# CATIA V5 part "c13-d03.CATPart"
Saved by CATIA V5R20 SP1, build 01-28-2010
Part number: Part1
Bounding box of the stored display mesh (mm): x 0 to 136, y 0 to 120, z 0 to 120
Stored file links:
  D:\v5_r20\psrt_files_downloaded\c13-catia-v5r20-prt\c13-catia-v5r20-figr-13-15 & 16\c13-d03.CATPart
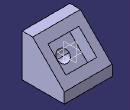
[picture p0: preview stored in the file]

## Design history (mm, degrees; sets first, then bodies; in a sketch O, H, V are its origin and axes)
Body1 (main body)
  Sketch1 on yz-plane, origin (0, 0, 0), H (0, 1, 0), V (0, 0, 1)
    line L1 (0, 0) -> (0, 120)
    line L2 (0, 120) -> (30, 120)
    line L3 (30, 120) -> (120, 30)
    line L4 (120, 30) -> (120, 0)
    point P4 (120, 0)
    line L5 (120, 0) -> (0, 0)
    length L1 = 120
    length L5 = 120
    length L4 = 30
    length L2 = 30
    vertical: L1 V, L4 V
    horizontal: L2 H, L5 H
    coincidence: P4 H
  Pad1: profile Sketch1, direction (1, 0, 0), length 136
  Sketch2 on face of Pad1, origin (0, 75, 75), H (-1, 0, 0), V (0, -0.7071, 0.7071)
    line L1 (-111.9577, 36.0679) -> (-24.0423, 36.0679)
    line L2 (-24.0423, 36.0679) -> (-24.0423, -36.0679)
    line L3 (-24.0423, -36.0679) -> (-111.9577, -36.0679)
    line L4 (-111.9577, -36.0679) -> (-111.9577, 36.0679)
    construction line L5 (-136, 63.6396) -> (0, -63.6396)
    point P5 (-136, 63.6396)
    point P6 (0, -63.6396)
    reference projected point E1 (0, -63.6396) from vertex [face of Pad1 | face of Pad1 | face of Pad1]
    reference projected point E2 (-136, 63.6396) from vertex [face of Pad1 | face of Pad1 | face of Pad1]
    axis line L6 (-111.9577, -36.0679) -> (-24.0423, 36.0679)
    point P7 (-68, 0)
    horizontal: L1 H, L3 H
    vertical: L2 V, L4 V
    coincidence: E1 P6, P5 E2
    midpoint: P7 L5, P7 L6
  Pocket1: profile Sketch2, direction (0, -0.7071, -0.7071), length 37
  Sketch3 on face of Pocket1, origin (0, 48.837, 48.837), H (-1, 0, 0), V (0, -0.7071, 0.7071)
    axis line L1 (-24.0423, -36.0679) -> (-111.9577, 36.0679)
    point P1 (-24.0423, -36.0679)
    point P2 (-111.9577, 36.0679)
    reference projected point E1 (-24.0423, -36.0679) from vertex [face of Pocket1 | face of Pad1 | face of Pocket1]
    reference projected point E2 (-111.9577, 36.0679) from vertex [face of Pocket1 | face of Pad1 | face of Pocket1]
    circle A1 centre (-68, 0) radius 17.073
    point P3 (-68, 0)
    point P4 (-50.927, 0)
    coincidence: P1 E1, P2 E2, A1 P4, P4 H
    midpoint: P3 L1
  Pocket2: profile Sketch3, direction (0, -0.7071, -0.7071), through (limit type 3)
